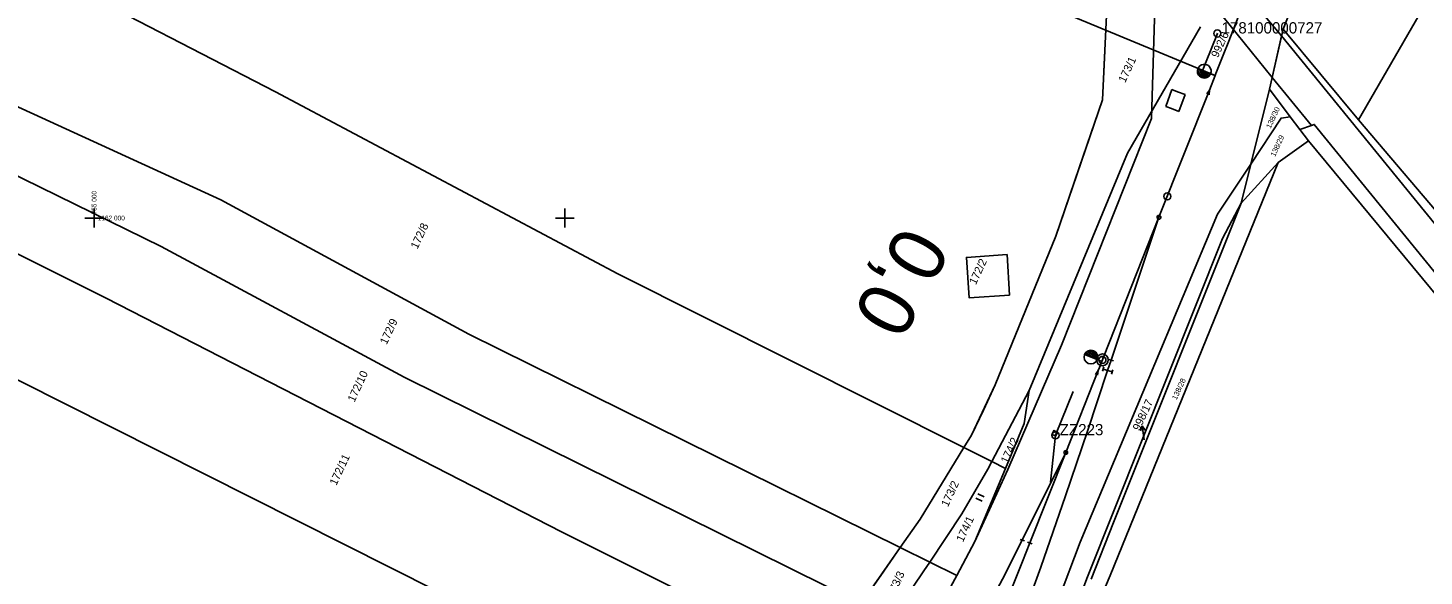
# Model space of a CAD drawing. Extents: x -755344 to -754412, y -1162670 to -1161477.
# Drawn here: x -755014.1 to -754717.5, y -1162076.1 to -1161959.6 of the extents above; entities that cross this region are included whole.
import ezdxf

# ---------------------------------------------------------------- set-up
doc = ezdxf.new("R2010")
doc.units = 0
for name, color, linetype in [('Body ŽBP', 7, 'Continuous'), ('hranice obvodu stavby', 7, 'Continuous'), ('Katastrální hranice', 7, 'Continuous'), ('Staniceni a namezniky', 7, 'Continuous'), ('Síť', 7, 'Continuous'), ('Vrstva 1', 7, 'Continuous'), ('Vrstva 12', 7, 'Continuous'), ('Vrstva 2', 7, 'Continuous'), ('Vrstva 3', 7, 'Continuous'), ('Vrstva 53', 7, 'Continuous'), ('Vrstva 55', 7, 'Continuous'), ('Vrstva 56', 7, 'Continuous'), ('Vrstva 57', 7, 'Continuous'), ('Vrstva 58', 7, 'Continuous')]:
    doc.layers.add(name, color=color, linetype=linetype)

msp = doc.modelspace()

# ---------------------------------------------------------------- linework, layer by layer
at = {"layer": 'Body ŽBP'}
for p, q in [((-754761.39, -1161960.77), (-754765.11, -1161970.05)), ((-754761.37, -1161960.72), (-754761.41, -1161960.81)), ((-754761.39, -1161960.77), (-754761.39, -1161960.77)), ((-754795.77, -1162046.18), (-754792.04, -1162036.9)), ((-754795.77, -1162046.18), (-754796.86, -1162056.12)), ((-754795.75, -1162046.13), (-754795.79, -1162046.22)), ((-754795.77, -1162046.18), (-754795.77, -1162046.18))]:
    msp.add_line(p, q, dxfattribs=at)
for centre in [(-754761.39, -1161960.77), (-754795.77, -1162046.18)]:
    msp.add_circle(centre, 0.756, dxfattribs=at)
at = {"layer": 'hranice obvodu stavby'}
for points in [[(-754764.52, -1161926.91), (-754785.9, -1161947.61), (-754784.8, -1161953.94), (-754785.29, -1161964.42), (-754785.77, -1161974.89), (-754790.73, -1161989.35), (-754795.69, -1162003.82), (-754802.15, -1162019.66), (-754808.6, -1162035.49), (-754811.09, -1162040.82), (-754813.58, -1162046.15), (-754815.21, -1162048.8)], [(-754812.88, -1162068.75), (-754805.89, -1162053.43), (-754794.46, -1162027.05), (-754775.38, -1161978.82), (-754774.5, -1161950.49), (-754763.88, -1161940.21)], [(-754815.21, -1162048.8), (-754824.54, -1162063.98), (-754828.75, -1162070.02), (-754832.91, -1162075.98), (-754837.06, -1162081.94), (-754845.89, -1162094.59), (-754854.71, -1162107.25), (-754856.54, -1162110.59), (-754858.37, -1162113.93), (-754862.06, -1162120.22), (-754865.75, -1162126.5), (-754867.08, -1162130.03), (-754868.4, -1162133.56), (-754868.42, -1162135.23)], [(-754882.86, -1162162.04), (-754882.32, -1162161.56), (-754868.56, -1162149.23), (-754865.36, -1162145.96), (-754862.16, -1162142.69), (-754850.97, -1162130.01), (-754843.96, -1162120.41), (-754829.74, -1162126.8), (-754821.22, -1162106.53), (-754831.28, -1162101.48), (-754823.58, -1162088.63), (-754816.76, -1162075.96)]]:
    msp.add_lwpolyline(points, dxfattribs=at)
at = {"layer": 'Katastrální hranice'}
for p, q in [((-754747.41, -1161959.83), (-754718.58, -1161886.73)), ((-754754.27, -1161988.55), (-754750.32, -1161972.64)), ((-754754.27, -1161988.55), (-754756.33, -1161996.85)), ((-754756.33, -1161996.85), (-754783.47, -1162064.75)), ((-754783.47, -1162064.75), (-754788.22, -1162076.73))]:
    msp.add_line(p, q, dxfattribs=at)
msp.add_lwpolyline([(-754750.32, -1161972.64), (-754749.74, -1161970.12), (-754747.74, -1161961.29), (-754747.41, -1161959.83)], dxfattribs=at)
at = {"layer": 'Staniceni a namezniky'}
for centre, radius in [((-754772.02, -1161995.39), 0.75), ((-754785.8, -1162030.15), 1.25), ((-754785.8, -1162030.15), 0.752)]:
    msp.add_circle(centre, radius, dxfattribs=at)
at = {"layer": 'Síť'}
for points in [[(-754998, -1162000), (-755000, -1162000), (-755002, -1162000)], [(-755000, -1161998), (-755000, -1162000), (-755000, -1162002)], [(-754898, -1162000), (-754900, -1162000), (-754902, -1162000)], [(-754900, -1161998), (-754900, -1162000), (-754900, -1162002)]]:
    msp.add_lwpolyline(points, dxfattribs=at)
at = {"layer": 'Vrstva 1'}
for p, q in [((-754761.85, -1161969.71), (-754761.68, -1161969.29)), ((-754785.93, -1162030.48), (-754785.58, -1162029.59))]:
    msp.add_line(p, q, dxfattribs=at)
for points in [[(-754761.68, -1161969.29), (-754760, -1161965.06), (-754759.09, -1161962.77), (-754756.79, -1161956.96), (-754754.25, -1161950.57), (-754752.63, -1161946.48), (-754752, -1161944.9), (-754751.26, -1161943.03), (-754747.59, -1161933.79), (-754744.07, -1161924.9), (-754742.14, -1161920.03), (-754738.48, -1161910.81), (-754735.14, -1161902.38), (-754733.34, -1161897.85), (-754731.73, -1161893.81)], [(-754785.58, -1162029.59), (-754773.79, -1161999.84), (-754763.07, -1161972.79), (-754761.85, -1161969.71)], [(-754783.95, -1162030.19), (-754773.79, -1161999.84), (-754763.07, -1161972.79), (-754761.85, -1161969.71)], [(-754802.82, -1162068.46), (-754793.59, -1162049.82), (-754786.7, -1162032.42), (-754786.45, -1162031.78), (-754785.93, -1162030.48)], [(-754801.21, -1162069.06), (-754793.59, -1162049.82), (-754786.7, -1162032.42), (-754786.45, -1162031.78), (-754785.93, -1162030.48)], [(-754788.99, -1162045.27), (-754784.69, -1162032.41), (-754783.95, -1162030.19)], [(-754814.09, -1162114.62), (-754808.25, -1162099.68), (-754804.47, -1162089.62), (-754798.9, -1162074.23), (-754793.63, -1162059.04), (-754788.99, -1162045.27)], [(-754802.82, -1162068.46), (-754807.01, -1162076.73), (-754811.35, -1162084.87), (-754815.39, -1162092.12), (-754818.66, -1162097.67), (-754820.65, -1162100.99), (-754825.85, -1162109.19), (-754831.64, -1162117.68), (-754836.49, -1162124.37), (-754839.8, -1162128.71), (-754840.46, -1162129.57), (-754840.79, -1162129.99), (-754847.19, -1162138.25), (-754849.01, -1162140.58), (-754849.98, -1162141.84), (-754854.92, -1162148.19), (-754860.18, -1162155.01)], [(-754855.13, -1162205.06), (-754851.41, -1162195.67), (-754847.87, -1162186.72), (-754844.23, -1162177.57), (-754840.47, -1162168.07), (-754836.48, -1162158.01), (-754832.73, -1162148.55), (-754829.03, -1162139.24), (-754824.91, -1162128.83), (-754821.22, -1162119.52), (-754818.37, -1162112.34), (-754814.26, -1162101.97), (-754810.6, -1162092.76), (-754806.3, -1162081.9), (-754802.77, -1162073.01), (-754801.21, -1162069.06)]]:
    msp.add_lwpolyline(points, dxfattribs=at)
at = {"layer": 'Vrstva 12'}
msp.add_lwpolyline([(-754796.55, -1162045.99), (-754795.73, -1162046.3), (-754795.34, -1162045.49), (-754796.1, -1162045.15), (-754796.55, -1162045.99)], dxfattribs=at)
at = {"layer": 'Vrstva 2'}
for p, q in [((-754761.85, -1161969.71), (-754807.93, -1161950.57)), ((-754764.89, -1161970.07), (-754765.59, -1161968.44)), ((-754762.81, -1161969.33), (-754765.54, -1161968.25)), ((-754764.4, -1161970.23), (-754765.2, -1161968.38)), ((-754763.99, -1161970.24), (-754764.7, -1161968.58)), ((-754763.62, -1161970.14), (-754764.2, -1161968.78)), ((-754763.29, -1161969.95), (-754763.71, -1161968.98)), ((-754763, -1161969.66), (-754763.21, -1161969.18)), ((-754762.81, -1161969.33), (-754761.85, -1161969.71)), ((-754783.95, -1162030.19), (-754773.79, -1161999.84)), ((-754789.6, -1162029.02), (-754786.89, -1162030.1)), ((-754789.25, -1162029.16), (-754789.44, -1162028.72)), ((-754788.76, -1162029.36), (-754789.16, -1162028.42)), ((-754788.27, -1162029.55), (-754788.84, -1162028.23)), ((-754787.77, -1162029.75), (-754788.47, -1162028.12)), ((-754787.28, -1162029.95), (-754788.07, -1162028.11)), ((-754786.85, -1162030), (-754787.6, -1162028.25)), ((-754786.89, -1162030.1), (-754785.93, -1162030.48)), ((-754785.11, -1162029.78), (-754786.04, -1162029.41)), ((-754783.48, -1162030.35), (-754784.43, -1162030.04)), ((-754802.82, -1162068.46), (-754793.59, -1162049.82)), ((-754802.35, -1162068.63), (-754803.3, -1162068.3)), ((-754800.74, -1162069.22), (-754801.69, -1162068.9))]:
    msp.add_line(p, q, dxfattribs=at)
for points in [[(-754785.58, -1162029.59), (-754773.79, -1161999.84), (-754763.07, -1161972.79), (-754761.85, -1161969.71)], [(-754763.13, -1161973.79), (-754763.07, -1161972.79), (-754763.62, -1161973.63)], [(-754801.21, -1162069.06), (-754793.59, -1162049.82), (-754786.7, -1162032.42), (-754786.45, -1162031.78), (-754785.93, -1162030.48)], [(-754786.82, -1162033.42), (-754786.7, -1162032.42), (-754787.3, -1162033.23)]]:
    msp.add_lwpolyline(points, dxfattribs=at)
for centre, radius in [((-754773.79, -1161999.84), 0.4), ((-754788.24, -1162029.56), 1.46), ((-754793.59, -1162049.82), 0.4)]:
    msp.add_circle(centre, radius, dxfattribs=at)
for centre, start, end in [((-754764.17, -1161968.78), 338.1527, 158.6222), ((-754764.17, -1161968.79), 158.407, 338.3679), ((-754788.24, -1162029.56), 338.2541, 158.2149)]:
    msp.add_arc(centre, 1.46, start, end, dxfattribs=at)
at = {"layer": 'Vrstva 3'}
for p, q in [((-754785.48, -1162031.62), (-754785.79, -1162032.57)), ((-754783.74, -1162032.72), (-754785.64, -1162032.09)), ((-754783.58, -1162032.25), (-754783.89, -1162033.2))]:
    msp.add_line(p, q, dxfattribs=at)
at = {"layer": 'Vrstva 53'}
for points in [[(-754717.5, -1161955.11), (-754731.42, -1161979.09), (-754747.41, -1161959.83), (-754749.74, -1161970.12), (-754750.32, -1161972.64), (-754745.89, -1161978.47), (-754747.84, -1161978.77), (-754754.27, -1161988.55), (-754756.33, -1161996.85), (-754760.29, -1162004.33), (-754789, -1162076.26), (-754793.13, -1162087.4), (-754798.15, -1162101.07), (-754802.96, -1162113.9), (-754816.22, -1162147.35), (-754851.45, -1162231.96), (-754887.61, -1162319.28)], [(-754837.06, -1162081.94), (-754828.75, -1162070.02), (-754822.47, -1162073.13), (-754816.76, -1162075.96), (-754812.88, -1162068.75), (-754806.4, -1162053.23), (-754809.29, -1162051.78), (-754815.21, -1162048.8), (-754813.58, -1162046.15), (-754808.6, -1162035.49), (-754795.69, -1162003.82), (-754785.77, -1161974.89), (-754784.8, -1161953.94)]]:
    msp.add_lwpolyline(points, dxfattribs=at)
at = {"layer": 'Vrstva 55'}
for p, q in [((-754747.41, -1161959.83), (-754718.58, -1161886.73)), ((-754747.41, -1161959.83), (-754718.58, -1161886.73)), ((-754717.5, -1161955.11), (-754731.42, -1161979.09)), ((-754731.42, -1161979.09), (-754747.41, -1161959.83)), ((-754754.27, -1161988.55), (-754750.32, -1161972.64)), ((-754754.27, -1161988.55), (-754750.32, -1161972.64)), ((-754750.32, -1161972.64), (-754745.89, -1161978.47)), ((-754745.89, -1161978.47), (-754743.83, -1161981.19)), ((-754689.56, -1162028.42), (-754731.42, -1161979.09)), ((-754743.83, -1161981.19), (-754742.02, -1161983.57)), ((-754742.02, -1161983.57), (-754748.48, -1161988.2)), ((-754748.48, -1161988.2), (-754784.18, -1162075.95)), ((-754748.48, -1161988.2), (-754756.33, -1161996.85)), ((-754754.27, -1161988.55), (-754756.33, -1161996.85)), ((-754754.27, -1161988.55), (-754756.33, -1161996.85)), ((-754756.33, -1161996.85), (-754783.47, -1162064.75)), ((-754756.33, -1161996.85), (-754783.47, -1162064.75)), ((-754809.29, -1162051.78), (-754801.36, -1162036.63)), ((-754815.21, -1162048.8), (-754809.29, -1162051.78)), ((-754806.4, -1162053.23), (-754809.29, -1162051.78)), ((-754783.47, -1162064.75), (-754788.22, -1162076.73)), ((-754783.47, -1162064.75), (-754788.22, -1162076.73)), ((-754828.75, -1162070.02), (-754837.06, -1162081.94)), ((-754828.75, -1162070.02), (-754822.47, -1162073.13)), ((-754822.47, -1162073.13), (-754816.76, -1162075.96)), ((-754816.76, -1162075.96), (-754823.58, -1162088.63)), ((-754784.18, -1162075.95), (-754785.12, -1162078.33))]:
    msp.add_line(p, q, dxfattribs=at)
for points in [[(-754790.69, -1161920.17), (-754784.8, -1161953.94), (-754785.77, -1161974.89), (-754795.69, -1162003.82), (-754808.6, -1162035.49), (-754813.58, -1162046.15), (-754815.21, -1162048.8)], [(-755049.81, -1161934.92), (-754992.75, -1161957.04), (-754961.49, -1161973.19), (-754888.73, -1162011.84), (-754815.21, -1162048.8)], [(-755055.25, -1161961.32), (-755018.7, -1161975.2), (-754973.07, -1161996.16), (-754920.4, -1162024.65), (-754828.75, -1162070.02)], [(-754764.95, -1161959.34), (-754780.44, -1161986.21), (-754801.36, -1162036.63)], [(-754750.32, -1161972.64), (-754749.74, -1161970.12), (-754747.74, -1161961.29), (-754747.41, -1161959.83)], [(-754750.32, -1161972.64), (-754749.74, -1161970.12), (-754747.74, -1161961.29), (-754747.41, -1161959.83)], [(-755057.47, -1161972.1), (-755029.84, -1161984.47), (-754985.77, -1162006.08), (-754934.11, -1162033.82), (-754837.06, -1162081.94)], [(-754745.89, -1161978.47), (-754747.84, -1161978.77), (-754754.27, -1161988.55)], [(-754597.36, -1162158.77), (-754599.91, -1162155.71), (-754609.7, -1162143.74), (-754612.4, -1162138.98), (-754625.61, -1162122.15), (-754652.5, -1162088.7), (-754680.12, -1162054.72), (-754695.96, -1162035.25), (-754716.99, -1162009.36), (-754740.8, -1161980.09), (-754741.4, -1161980.31), (-754743.83, -1161981.19)], [(-754742.02, -1161983.57), (-754691.91, -1162044.14), (-754615.21, -1162138.87)], [(-755060.88, -1161988.66), (-755029.34, -1162001.05), (-755021.14, -1162005.19), (-754997.44, -1162017.02), (-754900.68, -1162066.68), (-754845.66, -1162094.27)], [(-754978.01, -1162551.88), (-754981.37, -1162542.41), (-754930.02, -1162407.36), (-754870.17, -1162267.96), (-754836.4, -1162183.6), (-754824.89, -1162157.4), (-754808.97, -1162117.64), (-754790.52, -1162068.93), (-754761.32, -1161999.17), (-754754.27, -1161988.55)], [(-754789, -1162076.26), (-754760.29, -1162004.33), (-754756.33, -1161996.85)], [(-754805.56, -1162016.36), (-754806.06, -1162007.78), (-754814.69, -1162008.38), (-754814.09, -1162016.99), (-754805.56, -1162016.36)], [(-754858.37, -1162113.93), (-755045.32, -1162019.78), (-755064.79, -1162013.41)], [(-754801.36, -1162036.63), (-754802.42, -1162043.68), (-754806.4, -1162053.23)], [(-754815.21, -1162048.8), (-754824.54, -1162063.98), (-754828.75, -1162070.02)], [(-754822.47, -1162073.13), (-754815.64, -1162062.89), (-754810.12, -1162053.37), (-754809.29, -1162051.78)], [(-754806.4, -1162053.23), (-754812.88, -1162068.75), (-754816.76, -1162075.96)], [(-754830.58, -1162085.16), (-754823.72, -1162075.01), (-754822.47, -1162073.13)]]:
    msp.add_lwpolyline(points, dxfattribs=at)
at = {"layer": 'Vrstva 56'}
for p, q in [((-754747.74, -1161961.29), (-754755.18, -1161952.44)), ((-754749.74, -1161970.12), (-754763.11, -1161953.46)), ((-754747.74, -1161961.29), (-754721.12, -1161993.95)), ((-754749.74, -1161970.12), (-754741.4, -1161980.31)), ((-754772.36, -1161976.29), (-754771.05, -1161972.69)), ((-754771.05, -1161972.69), (-754769.84, -1161973.14)), ((-754769.84, -1161973.14), (-754768.22, -1161973.73)), ((-754768.22, -1161973.73), (-754769.56, -1161977.33)), ((-754771.12, -1161976.75), (-754772.36, -1161976.29)), ((-754769.56, -1161977.33), (-754771.12, -1161976.75)), ((-754721.12, -1161993.95), (-754599.09, -1162144.22))]:
    msp.add_line(p, q, dxfattribs=at)
at = {"layer": 'Vrstva 57'}
for p, q in [((-754777.34, -1162044.16), (-754777.71, -1162045.22)), ((-754776.95, -1162047.14), (-754777.34, -1162044.16)), ((-754777.34, -1162044.16), (-754776.71, -1162045.09))]:
    msp.add_line(p, q, dxfattribs=at)
at = {"layer": 'Vrstva 58'}
for p, q in [((-754811.33, -1162060.16), (-754812.69, -1162059.53)), ((-754810.9, -1162059.26), (-754812.26, -1162058.62))]:
    msp.add_line(p, q, dxfattribs=at)

# ---------------------------------------------------------------- texts
at = {"layer": 'Body ŽBP'}
for s, p in [(' 178100000727', (-754761.39, -1161960.77)), (' ZZ223', (-754795.77, -1162046.18))]:
    msp.add_text(s, height=2.4, dxfattribs=at).set_placement(p)
at = {"layer": 'Staniceni a namezniky'}
msp.add_text('0,0', height=12, rotation=241.5098, dxfattribs=at).set_placement((-754828.4, -1162001))
at = {"layer": 'Síť'}
for s, rotation, p in [('  755 000', 90, (-754999.5, -1162000)), ('  1162 000', 360, (-755000, -1162000.5))]:
    msp.add_text(s, height=1, rotation=rotation, dxfattribs=at).set_placement(p)
at = {"layer": 'Vrstva 57'}
for s, height, p in [('992/6', 1.7, (-754761.28, -1161966.06)), ('173/1', 1.7, (-754780.97, -1161971.37)), ('138/30', 1.139, (-754750.08, -1161981.08)), ('138/29', 1.139, (-754749.15, -1161987.06)), ('172/8', 1.7, (-754931.32, -1162006.71)), ('172/2', 1.7, (-754812.69, -1162014.3)), ('172/9', 1.7, (-754937.86, -1162027.04)), ('172/10', 1.7, (-754944.7, -1162039.26)), ('138/28', 1.139, (-754770.07, -1162038.77)), ('998/17', 1.7, (-754777.94, -1162045.36)), ('174/2', 1.7, (-754805.96, -1162052.31)), ('172/11', 1.7, (-754948.55, -1162056.98)), ('173/2', 1.7, (-754818.62, -1162061.53)), ('174/1', 1.7, (-754815.43, -1162069.02)), ('173/3', 1.7, (-754830.16, -1162080.73))]:
    msp.add_text(s, height=height, rotation=65, dxfattribs=at).set_placement(p)

doc.saveas('drawing.dxf')
